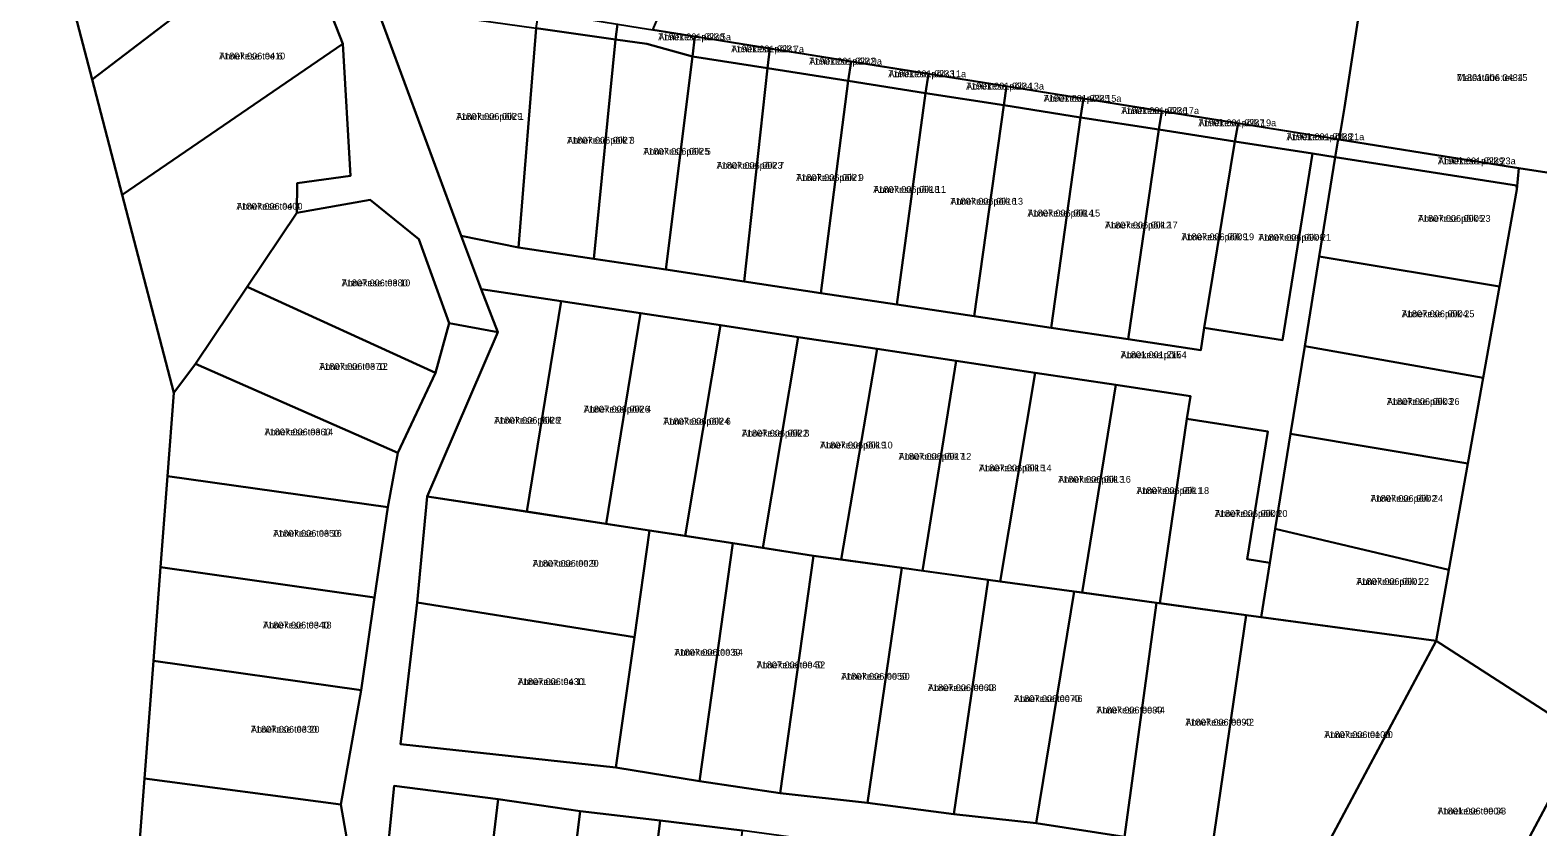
# Model space of a CAD drawing. Extents: x 529768 to 552006, y 6562269 to 6580975.
# Drawn here: x 537786.2 to 538116.9, y 6569464.5 to 6569639.3 of the extents above; entities that cross this region are included whole.
import ezdxf

# ---------------------------------------------------------------- set-up
doc = ezdxf.new("R2010")
doc.units = 0
for name, color, linetype in [('L_AADRESS', 7, 'Continuous'), ('PIIR', 7, 'Continuous'), ('TUNNUS', 7, 'Continuous')]:
    doc.layers.add(name, color=color, linetype=linetype)

msp = doc.modelspace()

# ---------------------------------------------------------------- linework, layer by layer
at = {"layer": 'PIIR'}
for points in [[(537816.02, 6569737.24), (537854.85, 6569674.57), (537867.75, 6569648.36), (537862.07, 6569644.64), (537880.68, 6569594.21), (537885.09, 6569582.46), (537888.74, 6569573.02), (537878.04, 6569575.03), (537871.43, 6569593.47), (537860.72, 6569602.1), (537844.63, 6569599.23), (537844.77, 6569605.73), (537856.47, 6569607.34), (537854.72, 6569636.33), (537844.48, 6569662.62), (537828.2, 6569691.04), (537822.42, 6569686.39), (537802.67, 6569727.76), (537801.82, 6569729.57)], [(537644.87, 6569513.8), (537745.56, 6569682.43), (537776.26, 6569709.01), (537777.15, 6569706.14), (537791.22, 6569661.26), (537799.74, 6569628.48), (537806.35, 6569603.16), (537817.69, 6569559.7), (537816.3, 6569541.46), (537814.78, 6569521.51), (537813.21, 6569500.95), (537811.25, 6569475.13), (537808.72, 6569441.91), (537816.76, 6569422.27), (537825.47, 6569401.03), (537829.72, 6569390.65), (537827.2, 6569384.07), (537652.4, 6569508.66), (537646.93, 6569512.39)], [(537951.39, 6569706.92), (538030.47, 6569682.43), (538028.39, 6569669.06), (538080.43, 6569660.96), (538078.27, 6569647.11), (538074.42, 6569622.33), (538073.31, 6569615.34), (537922.75, 6569639.42), (537924.05, 6569642.48)], [(537791.22, 6569661.26), (537822.42, 6569686.39), (537828.2, 6569691.04), (537844.48, 6569662.62), (537799.74, 6569628.48)], [(537799.74, 6569628.48), (537844.48, 6569662.62), (537854.72, 6569636.33), (537806.35, 6569603.16)], [(538078.27, 6569647.11), (538092.11, 6569644.96), (538092.65, 6569648.42), (538125.19, 6569643.36), (538120.73, 6569614.69), (538119.76, 6569607.91), (538112.71, 6569609.04), (538093.34, 6569612.14), (538073.31, 6569615.34), (538074.42, 6569622.33)], [(537862.07, 6569644.64), (537897.16, 6569639.73), (537893.27, 6569591.64), (537880.68, 6569594.21)], [(537900.66, 6569642.99), (537914.98, 6569640.66), (537914.57, 6569637.29), (537897.16, 6569639.73), (537897.72, 6569643.47), (537897.91, 6569643.44), (537898.52, 6569643.34)], [(537919.98, 6569639.84), (537922.75, 6569639.42), (537931.99, 6569637.94), (537931.47, 6569633.53), (537921.44, 6569636.33), (537914.57, 6569637.29), (537914.98, 6569640.66)], [(537897.16, 6569639.73), (537914.57, 6569637.29), (537909.82, 6569589.15), (537893.27, 6569591.64)], [(537914.57, 6569637.29), (537921.44, 6569636.33), (537931.47, 6569633.53), (537925.56, 6569586.77), (537909.82, 6569589.15)], [(537948.39, 6569635.32), (537947.86, 6569630.96), (537931.47, 6569633.53), (537931.99, 6569637.94), (537934, 6569637.62), (537934.42, 6569637.55)], [(537817.69, 6569559.7), (537806.35, 6569603.16), (537854.72, 6569636.33), (537856.47, 6569607.34), (537844.77, 6569605.73), (537844.63, 6569599.23), (537833.75, 6569582.99), (537822.47, 6569566.12)], [(537931.47, 6569633.53), (537947.86, 6569630.96), (537942.79, 6569584.18), (537925.56, 6569586.77)], [(537948.63, 6569635.28), (537949.8, 6569635.09), (537955.93, 6569634.11), (537960.38, 6569633.4), (537963.25, 6569632.94), (537963.67, 6569632.87), (537966.24, 6569632.46), (537965.56, 6569628.19), (537947.86, 6569630.96), (537948.39, 6569635.32)], [(537947.86, 6569630.96), (537965.56, 6569628.19), (537959.62, 6569581.64), (537942.79, 6569584.18)], [(537983.2, 6569629.75), (537982.57, 6569625.52), (537965.56, 6569628.19), (537966.24, 6569632.46)], [(537965.56, 6569628.19), (537982.57, 6569625.52), (537976.27, 6569579.13), (537959.62, 6569581.64)], [(538000.34, 6569627.01), (537999.7, 6569622.84), (537982.57, 6569625.52), (537983.2, 6569629.75)], [(538017.21, 6569624.31), (538016.56, 6569620.19), (537999.7, 6569622.84), (538000.34, 6569627.01)], [(537982.57, 6569625.52), (537999.7, 6569622.84), (537993.25, 6569576.57), (537976.27, 6569579.13)], [(538034.4, 6569621.56), (538033.7, 6569617.51), (538016.56, 6569620.19), (538017.21, 6569624.31)], [(537999.7, 6569622.84), (538016.56, 6569620.19), (538010.1, 6569574.03), (537993.25, 6569576.57)], [(538016.56, 6569620.19), (538033.7, 6569617.51), (538026.98, 6569571.48), (538010.1, 6569574.03)], [(538051.09, 6569618.89), (538050.37, 6569614.9), (538033.7, 6569617.51), (538034.4, 6569621.56), (538045.85, 6569619.73), (538048.8, 6569619.26), (538048.86, 6569619.25), (538048.93, 6569619.24)], [(538033.7, 6569617.51), (538050.37, 6569614.9), (538043.65, 6569574.03), (538042.9, 6569569.08), (538026.98, 6569571.48)], [(538073.03, 6569615.38), (538072.38, 6569611.45), (538067.44, 6569612.22), (538050.37, 6569614.9), (538051.09, 6569618.89)], [(538050.37, 6569614.9), (538067.44, 6569612.22), (538060.85, 6569571.26), (538043.65, 6569574.03)], [(538093.34, 6569612.14), (538112.71, 6569609.04), (538112.25, 6569604.38), (538112.14, 6569605.22), (538072.38, 6569611.45), (538073.03, 6569615.38), (538073.31, 6569615.34)], [(537880.68, 6569594.21), (537893.27, 6569591.64), (537909.82, 6569589.15), (537925.56, 6569586.77), (537942.79, 6569584.18), (537959.62, 6569581.64), (537976.27, 6569579.13), (537993.25, 6569576.57), (538010.1, 6569574.03), (538026.98, 6569571.48), (538042.9, 6569569.08), (538043.65, 6569574.03), (538060.85, 6569571.26), (538067.44, 6569612.22), (538072.38, 6569611.45), (538068.88, 6569589.68), (538065.71, 6569569.97), (538062.62, 6569550.75), (538059.26, 6569529.89), (538058.07, 6569522.46), (538053.13, 6569523.26), (538057.63, 6569551.22), (538039.88, 6569554.06), (538040.68, 6569559), (538024.3, 6569561.47), (538006.59, 6569564.14), (537989.24, 6569566.76), (537971.93, 6569569.37), (537954.65, 6569571.97), (537937.57, 6569574.55), (537920.05, 6569577.19), (537902.62, 6569579.82), (537885.09, 6569582.46)], [(538072.38, 6569611.45), (538112.14, 6569605.22), (538112.25, 6569604.38), (538108.45, 6569583.07), (538068.88, 6569589.68)], [(537844.63, 6569599.23), (537860.72, 6569602.1), (537871.43, 6569593.47), (537878.04, 6569575.03), (537875.09, 6569564.11), (537833.75, 6569582.99)], [(538068.88, 6569589.68), (538108.45, 6569583.07), (538104.87, 6569562.99), (538065.71, 6569569.97)], [(537833.75, 6569582.99), (537875.09, 6569564.11), (537866.85, 6569546.57), (537822.47, 6569566.12)], [(537885.09, 6569582.46), (537902.62, 6569579.82), (537895.1, 6569533.66), (537873.25, 6569537.02), (537888.74, 6569573.02)], [(537902.62, 6569579.82), (537920.05, 6569577.19), (537912.49, 6569530.98), (537895.1, 6569533.66)], [(537920.05, 6569577.19), (537937.57, 6569574.55), (537929.84, 6569528.32), (537922.01, 6569529.52), (537912.49, 6569530.98)], [(537937.57, 6569574.55), (537954.65, 6569571.97), (537946.87, 6569525.7), (537940.29, 6569526.71), (537929.84, 6569528.32)], [(537954.65, 6569571.97), (537971.93, 6569569.37), (537964.03, 6569523.15), (537957.98, 6569523.99), (537946.87, 6569525.7)], [(537971.93, 6569569.37), (537989.24, 6569566.76), (537981.92, 6569520.69), (537977.36, 6569521.31), (537964.03, 6569523.15)], [(538065.71, 6569569.97), (538104.87, 6569562.99), (538101.52, 6569544.2), (538062.62, 6569550.75)], [(537817.69, 6569559.7), (537822.47, 6569566.12), (537866.85, 6569546.57), (537864.61, 6569534.67), (537816.3, 6569541.46)], [(537989.24, 6569566.76), (538006.59, 6569564.14), (537998.96, 6569518.35), (537996.27, 6569518.72), (537981.92, 6569520.69)], [(538006.59, 6569564.14), (538024.3, 6569561.47), (538016.93, 6569515.9), (538015.12, 6569516.15), (537998.96, 6569518.35)], [(538024.3, 6569561.47), (538040.68, 6569559), (538039.88, 6569554.06), (538033.91, 6569513.57), (538033.21, 6569513.67), (538016.93, 6569515.9)], [(538039.88, 6569554.06), (538057.63, 6569551.22), (538053.13, 6569523.26), (538058.07, 6569522.46), (538056.15, 6569510.53), (538052.88, 6569510.98), (538033.91, 6569513.57)], [(538062.62, 6569550.75), (538101.52, 6569544.2), (538097.36, 6569520.89), (538059.26, 6569529.89)], [(537816.3, 6569541.46), (537864.61, 6569534.67), (537861.67, 6569514.85), (537814.78, 6569521.51)], [(537873.25, 6569537.02), (537922.01, 6569529.52), (537918.76, 6569506.13), (537871.09, 6569513.69)], [(537918.76, 6569506.13), (537922.01, 6569529.52), (537940.29, 6569526.71), (537933, 6569474.52), (537914.63, 6569477.53)], [(538059.26, 6569529.89), (538097.36, 6569520.89), (538094.58, 6569505.28), (538056.15, 6569510.53), (538058.07, 6569522.46)], [(537940.29, 6569526.71), (537957.98, 6569523.99), (537950.7, 6569471.87), (537933, 6569474.52)], [(537814.78, 6569521.51), (537861.67, 6569514.85), (537858.81, 6569494.52), (537813.21, 6569500.95)], [(537957.98, 6569523.99), (537977.36, 6569521.31), (537969.82, 6569469.76), (537950.7, 6569471.87)], [(537977.36, 6569521.31), (537996.27, 6569518.72), (537988.76, 6569467.28), (537969.82, 6569469.76)], [(537996.27, 6569518.72), (537998.96, 6569518.35), (538015.12, 6569516.15), (538006.8, 6569465.27), (537988.76, 6569467.28)], [(538015.12, 6569516.15), (538033.21, 6569513.67), (538026.22, 6569462.3), (538006.8, 6569465.27)], [(537871.09, 6569513.69), (537918.76, 6569506.13), (537914.63, 6569477.53), (537867.43, 6569482.62)], [(538033.21, 6569513.67), (538052.88, 6569510.98), (538045.42, 6569459.88), (538026.22, 6569462.3)], [(538045.42, 6569459.88), (538052.88, 6569510.98), (538094.58, 6569505.28), (538066.82, 6569453.38)], [(538094.58, 6569505.28), (538126.84, 6569484.47), (538096.86, 6569428.25), (538062.81, 6569445.87), (538066.82, 6569453.38)], [(537813.21, 6569500.95), (537858.81, 6569494.52), (537854.32, 6569469.37), (537811.25, 6569475.13)], [(537811.25, 6569475.13), (537854.32, 6569469.37), (537857.69, 6569450.14), (537808.72, 6569441.91)], [(537864.82, 6569461.87), (537866.03, 6569473.46), (537888.82, 6569470.57), (537882.09, 6569414.52), (537874.77, 6569415.32)], [(537888.82, 6569470.57), (537866.03, 6569473.46), (537864.82, 6569461.87), (537874.77, 6569415.32), (537880.93, 6569378.1), (537896.74, 6569361.67), (537916.15, 6569357.47), (537934.02, 6569355.27), (537952.81, 6569353.02), (537970.96, 6569350.8), (537989.52, 6569347.64), (537994.26, 6569347.32), (538027.94, 6569396.54), (538040.99, 6569451.4), (538014.18, 6569454.95), (537996.41, 6569456.59), (537978.62, 6569459.16), (537960.51, 6569461.22), (537942.31, 6569463.71), (537924.38, 6569465.87), (537906.84, 6569467.9)], [(537888.82, 6569470.57), (537906.84, 6569467.9), (537899.98, 6569412.55), (537882.09, 6569414.52)], [(537899.98, 6569412.55), (537906.84, 6569467.9), (537924.38, 6569465.87), (537917.49, 6569410.32), (537903.52, 6569411.99)], [(537917.49, 6569410.32), (537924.38, 6569465.87), (537942.31, 6569463.71), (537935.76, 6569408.45), (537922.27, 6569410.02)]]:
    msp.add_lwpolyline(points, close=True, dxfattribs=at)
for points in [[(538082.64, 6569084.58), (538063.49, 6569111.53), (537934.56, 6569291.38), (537959.31, 6569292.88), (537968.17, 6569294.43), (537973.98, 6569295.7), (537974.72, 6569296.39), (537976.43, 6569298), (537977.46, 6569298.96), (538000.62, 6569333.01), (538035.62, 6569382.26), (538037.93, 6569385.18), (538041.07, 6569383.44), (538066.31, 6569370.97), (538096.86, 6569428.25), (538126.84, 6569484.47), (538094.58, 6569505.28), (538097.36, 6569520.89), (538101.52, 6569544.2), (538104.87, 6569562.99), (538108.45, 6569583.07), (538112.25, 6569604.38), (538112.71, 6569609.04), (538119.76, 6569607.91)], [(537857.69, 6569450.14), (537854.32, 6569469.37), (537858.81, 6569494.52), (537861.67, 6569514.85), (537864.61, 6569534.67), (537866.85, 6569546.57), (537875.09, 6569564.11), (537878.04, 6569575.03), (537888.74, 6569573.02), (537873.25, 6569537.02), (537871.09, 6569513.69), (537867.43, 6569482.62), (537914.63, 6569477.53), (537933, 6569474.52), (537950.7, 6569471.87), (537969.82, 6569469.76), (537988.76, 6569467.28), (538006.8, 6569465.27), (538026.22, 6569462.3)]]:
    msp.add_lwpolyline(points, dxfattribs=at)

# ---------------------------------------------------------------- texts
at = {"layer": 'L_AADRESS'}
for s, p in [('Annekese põik 5a', (537923.93, 6569637.1)), ('Annekese tee 6', (537827.61, 6569632.89)), ('Annekese põik 7a', (537939.93, 6569634.45)), ('Annekese põik 9a', (537957.04, 6569631.76)), ('Annekese põik 11a', (537974.39, 6569628.99)), ('Annekese põik 13a', (537991.46, 6569626.29)), ('Metsatähe tee 15', (538099.08, 6569628.17)), ('Annekese põik 15a', (538008.46, 6569623.6)), ('Annekese põik 1', (537879.61, 6569619.64)), ('Annekese põik 17a', (538025.48, 6569620.91)), ('Annekese põik 19a', (538042.4, 6569618.23)), ('Annekese põik 3', (537903.92, 6569614.41)), ('Annekese põik 5', (537920.64, 6569611.98)), ('Annekese põik 21a', (538061.71, 6569615.17)), ('Annekese põik 7', (537936.71, 6569608.9)), ('Annekese põik 23a', (538094.93, 6569609.88)), ('Annekese põik 9', (537954.18, 6569606.22)), ('Annekese põik 11', (537971.09, 6569603.62)), ('Annekese tee 8', (537831.41, 6569599.92)), ('Annekese põik 13', (537987.99, 6569601.02)), ('Annekese põik 15', (538004.91, 6569598.42)), ('Annekese põik 17', (538021.9, 6569595.8)), ('Annekese põik 23', (538090.54, 6569597.26)), ('Annekese põik 19', (538038.67, 6569593.22)), ('Annekese põik 21', (538055.54, 6569593.1)), ('Annekese tee 10', (537854.49, 6569583.11)), ('Annekese põik 25', (538086.99, 6569576.33)), ('Annekese põik', (538025.34, 6569567.34)), ('Annekese tee 12', (537849.57, 6569564.78)), ('Annekese põik 26', (538083.73, 6569557.08)), ('Annekese põik 2', (537887.93, 6569552.96)), ('Annekese põik 4', (537907.57, 6569555.4)), ('Annekese põik 6', (537925.03, 6569552.75)), ('Annekese tee 14', (537837.57, 6569550.4)), ('Annekese põik 8', (537942.25, 6569550.13)), ('Annekese põik 10', (537959.4, 6569547.52)), ('Annekese põik 12', (537976.64, 6569545.04)), ('Annekese põik 14', (537994.26, 6569542.5)), ('Annekese põik 16', (538011.63, 6569540)), ('Annekese põik 18', (538028.8, 6569537.53)), ('Annekese põik 24', (538080.12, 6569535.82)), ('Annekese põik 20', (538045.99, 6569532.5)), ('Annekese tee 16', (537839.46, 6569528.16)), ('Annekese tee 9', (537896.36, 6569521.57)), ('Annekese põik 22', (538077.03, 6569517.59)), ('Annekese tee 18', (537837.23, 6569508.02)), ('Annekese tee 54', (537927.46, 6569502.05)), ('Annekese tee 52', (537945.49, 6569499.28)), ('Annekese tee 50', (537964.03, 6569496.78)), ('Annekese tee 11', (537893.1, 6569495.61)), ('Annekese tee 48', (537983.05, 6569494.28)), ('Annekese tee 46', (538001.94, 6569491.88)), ('Annekese tee 44', (538020, 6569489.37)), ('Annekese tee 42', (538039.55, 6569486.71)), ('Annekese tee 20', (537834.58, 6569485.16)), ('Annekese tee 40', (538070, 6569483.98)), ('Annekese tee 38', (538094.83, 6569467.21))]:
    msp.add_text(s, height=1.5, dxfattribs=at).set_placement(p)
at = {"layer": 'TUNNUS'}
for s, p in [('71901:001:0230', (537923.93, 6569637.1)), ('71807:006:0410', (537827.61, 6569632.89)), ('71901:001:0231', (537939.93, 6569634.45)), ('71901:001:0232', (537957.04, 6569631.76)), ('71901:001:0233', (537974.39, 6569628.99)), ('71901:001:0234', (537991.46, 6569626.29)), ('71801:006:0434', (538099.08, 6569628.17)), ('71901:001:0235', (538008.46, 6569623.6)), ('71807:006:0029', (537879.61, 6569619.64)), ('71901:001:0236', (538025.48, 6569620.91)), ('71901:001:0237', (538042.4, 6569618.23)), ('71807:006:0027', (537903.92, 6569614.41)), ('71901:001:0238', (538061.71, 6569615.17)), ('71807:006:0025', (537920.64, 6569611.98)), ('71807:006:0023', (537936.71, 6569608.9)), ('71901:001:0239', (538094.93, 6569609.88)), ('71807:006:0021', (537954.18, 6569606.22)), ('71807:006:0018', (537971.09, 6569603.62)), ('71807:006:0400', (537831.41, 6569599.92)), ('71807:006:0016', (537987.99, 6569601.02)), ('71807:006:0014', (538004.91, 6569598.42)), ('71807:006:0012', (538021.9, 6569595.8)), ('71807:006:0005', (538090.54, 6569597.26)), ('71807:006:0009', (538038.67, 6569593.22)), ('71807:006:0006', (538055.54, 6569593.1)), ('71807:006:0380', (537854.49, 6569583.11)), ('71807:006:0004', (538086.99, 6569576.33)), ('71801:001:2154', (538025.34, 6569567.34)), ('71807:006:0370', (537849.57, 6569564.78)), ('71807:006:0003', (538083.73, 6569557.08)), ('71807:006:0028', (537887.93, 6569552.96)), ('71807:006:0026', (537907.57, 6569555.4)), ('71807:006:0024', (537925.03, 6569552.75)), ('71807:006:0360', (537837.57, 6569550.4)), ('71807:006:0022', (537942.25, 6569550.13)), ('71807:006:0019', (537959.4, 6569547.52)), ('71807:006:0017', (537976.64, 6569545.04)), ('71807:006:0015', (537994.26, 6569542.5)), ('71807:006:0013', (538011.63, 6569540)), ('71807:006:0011', (538028.8, 6569537.53)), ('71807:006:0002', (538080.12, 6569535.82)), ('71807:006:0008', (538045.99, 6569532.5)), ('71807:006:0350', (537839.46, 6569528.16)), ('71807:006:0020', (537896.36, 6569521.57)), ('71807:006:0001', (538077.03, 6569517.59)), ('71807:006:0340', (537837.23, 6569508.02)), ('71807:006:0030', (537927.46, 6569502.05)), ('71807:006:0040', (537945.49, 6569499.28)), ('71807:006:0050', (537964.03, 6569496.78)), ('71807:006:0430', (537893.1, 6569495.61)), ('71807:006:0060', (537983.05, 6569494.28)), ('71807:006:0070', (538001.94, 6569491.88)), ('71807:006:0080', (538020, 6569489.37)), ('71807:006:0090', (538039.55, 6569486.71)), ('71807:006:0330', (537834.58, 6569485.16)), ('71807:006:0100', (538070, 6569483.98)), ('71801:006:0904', (538094.83, 6569467.21))]:
    msp.add_text(s, height=1.5, dxfattribs=at).set_placement(p)

doc.saveas('drawing.dxf')
